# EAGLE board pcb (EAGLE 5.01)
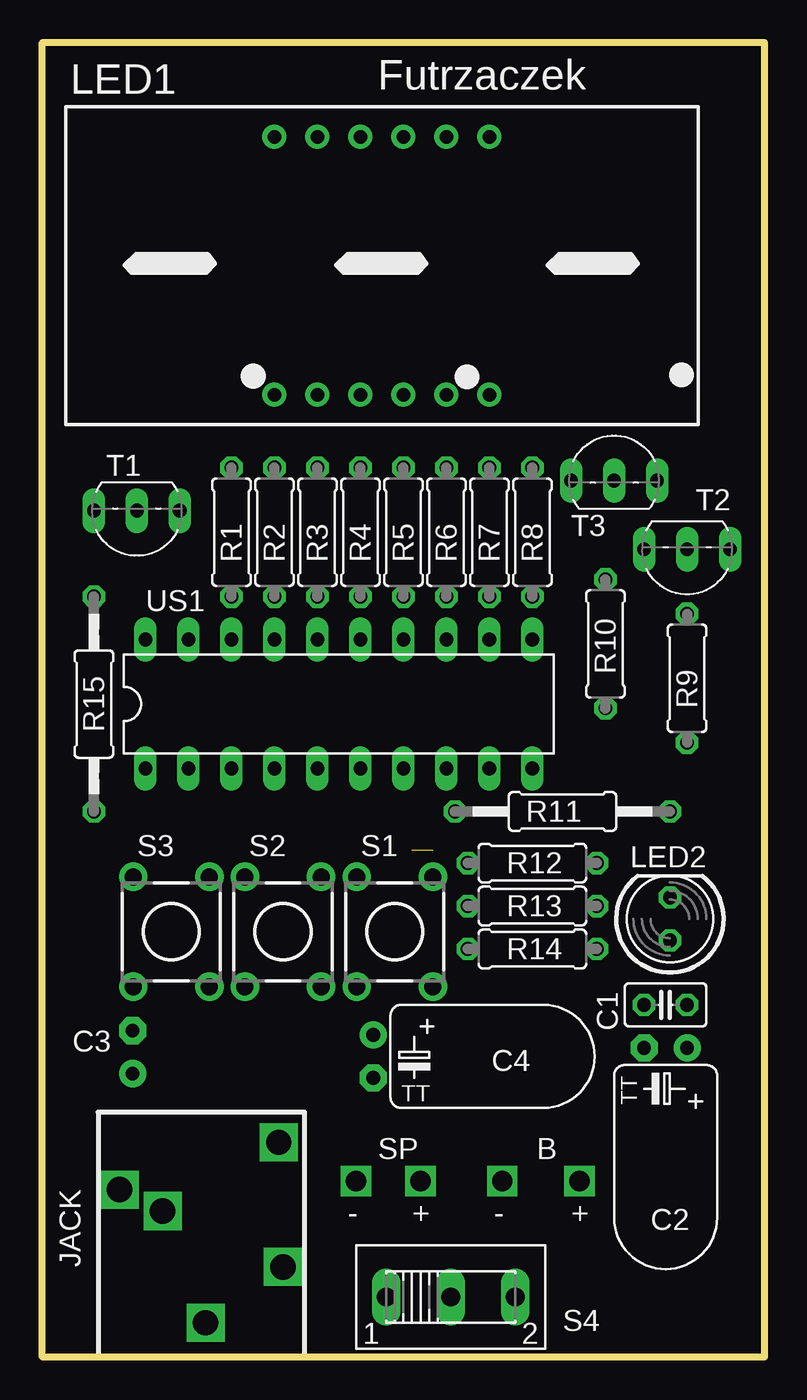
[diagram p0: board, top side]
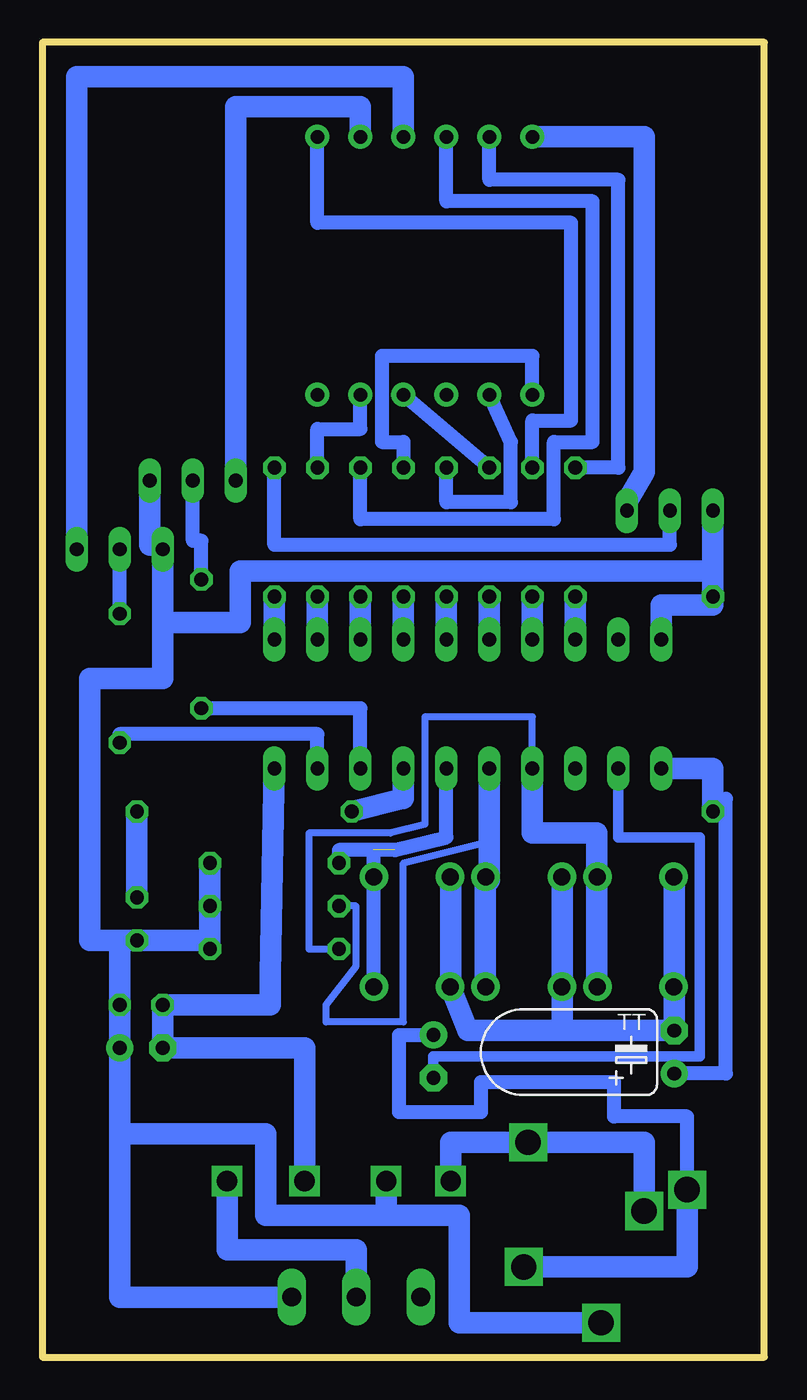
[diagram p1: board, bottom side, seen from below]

Size 42.67 x 77.72 mm. Coordinates in mm from the lower left corner, seen from the top.
Outline: 0,77.72 42.67,77.72 42.67,0 0,0 0,77.72
Copper layers (1*16): Top 0.035mm / dielectric 1.5mm / Bottom 0.035mm
Design rules "default": minimum track width 10mil, minimum drill 24mil, track to track 8mil, track to pad 8mil, pad to pad 8mil, via to via 8mil, smd to smd 8mil, copper to edge 40mil, drill to drill 8mil, minimum pad ring 10mil, minimum via ring 8mil, stop-mask expansion 4mil, vias tented up to drill 0mil, thermal gap 10mil

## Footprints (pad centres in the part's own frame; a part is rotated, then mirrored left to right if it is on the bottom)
C025-025X050 = drill 0.813 octagon: 1 -1.27,0; 2 1.27,0
TT2D6L = drill 0.813 pad 1.6 round: + -1.27,0 | drill 0.813 pad 1.6 octagon: - 1.27,0
TT2D5L = drill 0.813 pad 1.6 round: + -1.27,0 | drill 0.813 pad 1.6 octagon: - 1.27,0
BX56-12 = drill 0.8 pad 1.422 round: 1 -6.35,-7.62; 2 -3.81,-7.62; 3 -1.27,-7.62; 4 1.27,-7.62; 5 3.81,-7.62; 6 6.35,-7.62; 7 6.35,7.62; 8 3.81,7.62; 9 1.27,7.62; 10 -1.27,7.62; 11 -3.81,7.62; 12 -6.35,7.62
LED5MM = drill 0.813 octagon: A -1.27,0; K 1.27,0
0207/7 = drill 0.813 octagon: 1 -3.81,0; 2 3.81,0
0207/12 = drill 0.813 octagon: 1 -6.35,0; 2 6.35,0
TL1105 = drill 1 pad 1.676 round: 1 -2.25,3.25; 2 2.25,3.25; 3 -2.25,-3.25; 4 2.25,-3.25
255SB = drill 1.118 long: 1 -3.81,0; 2 0,0; 3 3.81,0
TO92-BCE = drill 0.813 long: B 2.54,0; C 0,0; E -2.54,0
DIL20 = drill 0.813 long: 1 -11.43,-3.81; 2 -8.89,-3.81; 3 -6.35,-3.81; 4 -3.81,-3.81; 5 -1.27,-3.81; 6 1.27,-3.81; 7 3.81,-3.81; 8 6.35,-3.81; 9 8.89,-3.81; 10 11.43,-3.81; 11 11.43,3.81; 12 8.89,3.81; 13 6.35,3.81; 14 3.81,3.81; 15 1.27,3.81; 16 -1.27,3.81; 17 -3.81,3.81; 18 -6.35,3.81; 19 -8.89,3.81; 20 -11.43,3.81

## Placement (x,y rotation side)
C1  [C025-025X050]  36.83,20.83 0 top
C2  [TT2D6L]  36.83,18.29 180 top
C4  [TT2D6L]  19.56,17.78 270 top
E$29  [TT2D5L]  5.33,18.03 90 bottom
LED1  [BX56-12]  20.07,64.52 0 top
LED2  [LED5MM]  37.08,25.91 90 top
R1  [0207/7]  11.18,48.77 90 top
R2  [0207/7]  13.72,48.77 90 top
R3  [0207/7]  16.26,48.77 90 top
R4  [0207/7]  18.8,48.77 90 top
R5  [0207/7]  21.34,48.77 90 top
R6  [0207/7]  23.88,48.77 90 top
R7  [0207/7]  26.42,48.77 90 top
R8  [0207/7]  28.96,48.77 90 top
R9  [0207/7]  38.1,40.13 90 top
R10  [0207/7]  33.27,42.16 90 top
R11  [0207/12]  30.73,32.26 180 top
R12  [0207/7]  28.96,29.21 180 top
R13  [0207/7]  28.96,26.67 180 top
R14  [0207/7]  28.96,24.13 180 top
R15  [0207/12]  3.05,38.61 90 top
S1  [TL1105]  20.83,25.15 180 top
S2  [TL1105]  14.22,25.15 180 top
S3  [TL1105]  7.62,25.15 180 top
S4  [255SB]  24.13,3.56 0 top
T1  [TO92-BCE]  5.59,50.04 180 top
T2  [TO92-BCE]  38.1,47.75 180 top
T3  [TO92-BCE]  33.78,51.82 0 top
US1  [DIL20]  17.53,38.61 0 top

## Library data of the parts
C1 C2 C4 E$29 R1-R15 = rcl
LED1 = display-kingbright
LED2 = led
S1-S4 = switch
T1-T3 = transistor-npn
US1 = 40xx

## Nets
S$1: R1.1 US1.18
S$2: R2.1 US1.17
S$3: R3.1 US1.16
S$4: R4.1 US1.15
S$5: R5.1 US1.14
S$6: R6.1 US1.13
S$7: R7.1 US1.12
S$8: LED1.11 R1.2
S$9: LED1.7 R2.2
S$10: LED1.4 R3.2
S$11: LED1.2 R4.2
S$12: LED1.1 R5.2
S$13: LED1.10 R6.2
S$14: LED1.5 R7.2
S$15: R8.1 US1.11
S$16: R8.2
S$17: LED1.12
S$18: R11.2
S$19: R9.1 US1.9
S$20: R10.1 US1.8
S$21: LED1.9
S$22: LED1.8
S$23: C2.+ LED2.A R12.1 R14.1 S4.3
S$24: R10.2
S$25: R9.2 T2.C
S$26: R15.1 US1.1
S$28: LED2.K R11.1
S$29: R13.2
S$30: R12.2
S$31: C4.- US1.2
S$32: R14.2 US1.4
S$33: C1.1 C2.-
S$39: C4.+
S$44: S4.2

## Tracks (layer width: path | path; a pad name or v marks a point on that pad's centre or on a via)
S$1
  Bottom 1.27: US1.18 R1.1
S$2
  Bottom 1.27: US1.17 R2.1
S$3
  Bottom 1.27: US1.16 R3.1
S$4
  Bottom 1.27: US1.15 R4.1
S$5
  Bottom 1.27: US1.14 R5.1
S$6
  Bottom 1.27: US1.13 R6.1
S$7
  Bottom 1.27: US1.12 R7.1
S$8
  Bottom 0.813: LED1.11 16.26,69.6 8.64,69.6 8.64,52.58 R1.2
S$9
  Bottom 0.813: LED1.7 26.42,67.06 11.43,67.06 11.43,55.37 13.72,55.37 R2.2
S$10
  Bottom 0.813: R3.2 LED1.4
S$11
  Bottom 0.813: R4.2 18.8,50.55 14.99,50.55 14.99,54.1 LED1.2
S$12
  Bottom 0.813: LED1.1 13.72,59.18 22.61,59.18 22.61,54.1 21.34,54.1 R5.2
S$13
  Bottom 0.813: LED1.10 18.8,68.33 10.16,68.33 10.16,54.1 12.45,54.1 12.45,49.53 23.88,49.53 R6.2
S$14
  Bottom 0.813: R7.2 26.42,54.86 23.88,54.86 LED1.5
S$15
  Bottom 1.27: US1.11 R8.1
S$16
  Bottom 0.813: 5.59,49.53 5.59,48.01 28.96,48.01 R8.2
S$17
  Bottom 1.27: LED1.12 7.11,72.14 7.11,52.32 8.13,50.55
S$18
  Bottom 1.27: R11.2 21.34,33.02 21.34,35.05
S$19
  Bottom 0.813: US1.9 26.42,36.83 38.1,36.83 R9.1
S$20
  Bottom 0.813: R10.1 23.88,38.35 US1.8
S$21
  Bottom 1.27: LED1.9 21.34,75.69 40.64,75.69 40.64,47.24
S$22
  Bottom 1.27: LED1.8 23.88,73.91 31.24,73.91 31.24,51.31
S$23
  Bottom 1.27: 36.32,51.31 36.32,48.01 35.56,48.01 35.56,43.43 | 35.56,43.43 35.56,40.13 39.88,40.13 39.88,24.64 38.1,24.64 | 35.56,43.43 30.99,43.43 30.99,46.48 3.05,46.48 | 3.05,46.48 3.05,50.29 | 6.1,41.91 6.1,44.45 3.05,44.45 3.05,46.48 | 38.1,24.64 LED2.A 32.77,24.64 | 32.77,24.64 R14.1 | 32.77,24.64 R12.1 | 38.1,24.64 C2.+ 38.1,3.56 S4.3
S$24
  Bottom 0.813: R10.2 33.27,48.26 33.78,48.26 33.78,50.8
S$25
  Bottom 0.813: R9.2 T2.C
S$26
  Bottom 1.27: US1.1 3.05,34.8 R15.1
S$27
  Bottom 1.27: 29.21,22.61 28.96,35.05
S$28
  Bottom 1.27: LED2.K R11.1
S$29
  Bottom 0.406: R13.2 24.13,26.67 24.13,23.11 25.91,20.83 25.91,19.81 21.34,19.81 21.34,29.21 16.26,30.48
  Bottom 0.61: 16.26,30.48 16.26,28.45
  Bottom 1.27: 16.26,28.19 16.26,30.48 16.26,34.8
S$30  (1 unrouted)
  Bottom 0.61: 21.84,29.97 19.05,30.73
  Bottom 0.813: 18.8,34.8 18.8,30.73 21.84,29.97 25.15,29.97 R12.2 | 23.11,29.97 23.11,21.84
S$31
  Bottom 0.61: US1.2 8.64,30.73 3.81,30.73 3.81,17.78 19.56,17.78 C4.-
S$32
  Bottom 0.406: R14.2 26.92,24.13 26.92,30.99 22.1,30.99 20.07,31.5 20.07,37.85 13.72,37.85 US1.4
  Bottom 1.27: US1.4 13.72,30.99 9.91,30.99 9.91,21.84
S$33
  Bottom 1.27: 29.21,22.86 29.21,20.83 C1.1 C2.- 27.18,18.29 27.18,10.16
S$36
  Bottom 0.813: 2.29,33.02 2.29,16.76 5.59,16.76
S$37
  Bottom 1.27: 4.57,9.91 4.57,5.33 14.22,5.33
S$38
  Bottom 1.27: 7.11,8.64 7.11,12.7 13.97,12.7
S$39  (via drill 1.5)
  Bottom 0.813: C4.+ 21.59,19.05 21.59,14.48 16.76,14.48 16.76,16.26 8.89,16.26 8.89,14.22 4.57,14.22 v4.57,9.91
S$40  (via drill 1.5)
  other vias: 7.11,8.64
S$41  (via drill 1.2, 1.5)
  Bottom 1.27: v13.97,12.7 18.54,12.7 v18.54,10.41
S$42  (via drill 1.5)
  other vias: 14.22,5.33
S$43  (via drill 1.2, 1.5)
  Bottom 1.27: 22.35,8.38 18.03,8.38 18.03,2.03 v9.65,2.03 | 22.35,8.38 v22.35,10.41 | 22.35,8.38 29.46,8.38 29.46,13.21 37.85,13.21
S$44  (via drill 1.2)
  Bottom 1.27: v31.75,10.41 31.75,6.35 24.13,6.35 S4.2
S$45  (via drill 1.2)
  other vias: 27.18,10.41
S$46
  Bottom 1.27: 16.51,21.84 16.51,28.45
S$47
  Bottom 1.27: 18.54,28.45 18.54,21.84 17.53,19.3 11.94,19.3 | 11.94,19.3 11.94,28.45 | 5.33,28.45 5.33,19.3 11.43,19.3 11.68,19.3 11.94,19.3

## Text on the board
tNames: Futrzaczek | C3 | SP | B | - | + | - | + | JACK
